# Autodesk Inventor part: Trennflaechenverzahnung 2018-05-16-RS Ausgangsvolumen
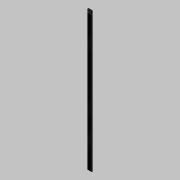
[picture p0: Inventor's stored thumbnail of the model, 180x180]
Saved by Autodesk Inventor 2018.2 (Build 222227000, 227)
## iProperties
Created: 2018-05
Part Number: Trennflaechenverzahnung 2018-05-16-RS Ausgangsvolumen
Material: ---
Document SubType Name: Modeling
Designer: Roland
Appearance: grau
Sending System: Autodesk Inventor 2011
Preprocessor: Autodesk Inventor 2011
xyz-Box: 27 x 510 x 15
Title: C:\Users\epping\Desktop\RE-ENG-043744 komplett.stp
Author: dehorsoep
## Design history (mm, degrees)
node "Blöcke"
  sketch "Rechteck abgerundet"
    geometry: L1 (182.926, 40.686)-(222.735, 40.686); L2 (229.51, 47.461)-(229.51, 80.56); L3 (176.151, 47.461)-(176.151, 80.56); L4 (182.926, 87.335)-(222.735, 87.335); A1 r 6.775 centre (222.735, 47.461) between (222.735, 40.686) and (229.51, 47.461); A2 r 6.775 centre (222.735, 80.56) between (229.51, 80.56) and (222.735, 87.335); A3 r 6.775 centre (182.926, 47.461) between (176.151, 47.461) and (182.926, 40.686); A4 r 6.775 centre (182.926, 80.56) between (182.926, 87.335) and (176.151, 80.56); 1 further point
    constraints: 8 end point, 8 point on circle, 8 tangent, 4 centre point, 3 equal radius, 3 perpendicular, 1 coincident
feature "PROFIL_ATKA"
node "Volumen1"
